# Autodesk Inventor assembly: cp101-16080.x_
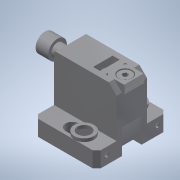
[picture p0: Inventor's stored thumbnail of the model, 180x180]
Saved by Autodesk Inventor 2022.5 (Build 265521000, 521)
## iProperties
Part Number: cp101-16080.x_
Material: 一般
Document SubType Name: Assembly
Designer: ImaoCorp
Sending System: SOLIDWORKS 2017-2017317
MC: AMD64
MC_MODEL: Intel64 Family 6 Model 60 Stepping 3, GenuineIntel
OS: Windows_NT
FRU: Parasolid Version 29.0, build 201,  4-17-2017
FORMAT: text
GUISE: transmit
KEY: cp101-16080
FILE: cp101-16080.x_t
DATE: Thu Apr 04 16:34:43 2019
Author: ImaoCorp
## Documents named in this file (5)
- X:\14_SW2022-Inv2022\00_全2023-1023新製品(TCC)まで\c\cp101-16080\CP101-16080.iam
- X:\14_SW2022-Inv2022\00_全2023-1023新製品(TCC)まで\c\cp101-16080\cp101-16080_01.ipt
- X:\14_SW2022-Inv2022\00_全2023-1023新製品(TCC)まで\c\cp101-16080\cp101-16080_02.ipt
- X:\14_SW2022-Inv2022\00_全2023-1023新製品(TCC)まで\c\cp101-16080\cp101-16080_03.ipt
- X:\14_SW2022-Inv2022\00_全2023-1023新製品(TCC)まで\c\cp101-16080\cp101-16080_04.ipt
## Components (4 placed, 4 different names)
1. cp101-16080_01
2. cp101-16080_02
3. cp101-16080_03
4. cp101-16080_04
